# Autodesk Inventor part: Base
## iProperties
Shininess: 77.0
Length Units: 11269
Angle Units: 11279
Time Units: 11290
Mass Units: 11283
Length Display Precision: 3
Angle Display Precision: 2
Created: 2002-02
Part Number: Base
Document SubType Name: Modeling
Designer: ***
Density: 1 g/cm^3
Density: 0.0
Volumn: 0.0
Area: 0.0
PropertySet Name: Model Information
Control State: 0
Master: False
Checked Out: False
Author: ***
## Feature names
1. Extrusion1
2. Extrusion2
3. Extrusion3
4. Hole1
5. Mirror1
6. Extrusion4
7. Extrusion5
